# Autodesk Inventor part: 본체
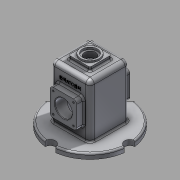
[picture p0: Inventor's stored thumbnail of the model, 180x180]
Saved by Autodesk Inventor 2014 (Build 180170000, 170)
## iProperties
Created: 2018-07
Part Number: 본체
Material: Aluminum 6061
Document SubType Name: Modeling
Designer: user
Density: 2.71 g/cm^3
Appearance: Aluminum - Flat
Mass: 923.886 g
Surface Area: 1002.83 cm^2
Volume: 340.917 cm^3
Author: user
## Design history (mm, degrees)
sketch "Sketch1"
  geometry: C1 r 75 at (0, 0); 1 further point
  constraints: 1 centre point, 1 coincident
  dimensions: "d0" = 150 diameter of C1
extrude "Extrusion1" new body sketch "Sketch1" distance "d1" = 10; taper "d2" = 0 deg
sketch "Sketch2"
  geometry: L1 (0, 0)-(0, 121.11); C1 r 10 at (0, 75)
  constraints: 2 end point, 1 centre point, 1 vertical, 1 vertical alignment, 1 other
  dimensions: "d3" = 20 diameter of C1; "d4" = 0 distance from line of C1.centre L1
extrude "Extrusion2" cut sketch "Sketch2" distance "d5" = 10; taper "d6" = 0 deg
pattern_circular "Circular Pattern1" dims angle "d8" = 360 deg
sketch "Sketch3"
  geometry: L1 (-37, 37)-(37, 37); L2 (37, 37)-(37, -37); L3 (37, -37)-(-37, -37); L4 (-37, -37)-(-37, 37); L5 (0, 0)-(153.232, 0); L6 (0, 0)-(0, 243.546); A1 r 75 centre (0, 0) between (9.978, -74.333) and (74.333, -9.978) reference
  constraints: 12 end point, 3 perpendicular, 2 parallel, 1 horizontal, 2 other
  dimensions: "d10" = 74 distance between parallel lines of L4 L2; "d11" = 74 distance between parallel lines of L3 L1
extrude "Extrusion3" join sketch "Sketch3" distance "d12" = 100; taper "d13" = 0 deg
workplane "Work Plane1"
sketch "Sketch4"
  geometry: L1 (12, 70)-(62, 70); L2 (62, 70)-(62, 20); L3 (62, 20)-(12, 20); L4 (12, 20)-(12, 70); L5 (-38.534, 45)-(101.823, 45); L6 (37, 113.812)-(37, 3.906); L7 (46.978, -10)-(111.333, -10) reference; L8 (74, 0)-(74, 100) reference; 1 further point
  constraints: 12 end point, 3 perpendicular, 2 parallel, 1 horizontal, 2 other
  dimensions: "d16" = 50 distance between parallel lines of L3 L1; "d17" = 50 distance between parallel lines of L4 L2; "d18" = 55 distance between parallel lines of L5 L7; "d20" = 37 distance between parallel lines of L6 L8
extrude "Extrusion4" join sketch "Sketch4" distance "d21" = 100; taper "d22" = 0 deg
sketch "Sketch5"
  geometry: L1 (-12, 70)-(-62, 70) reference; L2 (-12, 20)-(-12, 70) reference; C1 r 16 at (-37, 45); 1 further point
  constraints: 1 centre point
  dimensions: "d23" = 32 diameter of C1; "d26" = 25 distance from line of L2 C1.centre; "d27" = 25 distance from line of C1.centre L1
extrude "Extrusion5" cut sketch "Sketch5" distance "d28" = 100; taper "d29" = 0 deg
chamfer "Chamfer1" distance "d30" = 1; stored, may be unused: second distance "d31" = 2, angle "d32" = 45 deg
fillet "Fillet1" dims "d33" = 6
fillet "Fillet2" dims "d34" = 3
sketch "Sketch6"
  geometry: A1 r 6 centre (18, 26) between (12, 26) and (18, 20) reference; A2 r 6 centre (56, 26) between (56, 20) and (62, 26) reference; A3 r 6 centre (56, 64) between (62, 64) and (56, 70) reference; A4 r 6 centre (18, 64) between (18, 70) and (12, 64) reference; 5 further points
  constraints: 4 coincident
hole "Hole1" sketch "Sketch6" at (18, 64), (56, 64), (56, 26), (18, 26) diameter "d35" = 3.242; stored, may be unused: countersink angle "d39" = 82 deg, drill point angle "d41" = 118 deg; dims "d36" = 8, "d37" = 3.023, "d38" = 2, "d40" = 10
mirror "Mirror1"
fillet "Fillet3" dims "d42" = 8
fillet "Fillet4" dims "d43" = 8
fillet "Fillet5" dims "d44" = 3
fillet "Fillet6" dims "d45" = 3
sketch "Sketch7"
  geometry: L1 (-20, 20)-(20, 20); L2 (20, 20)-(20, -20); L3 (20, -20)-(-20, -20); L4 (-20, -20)-(-20, 20); 1 further point
  constraints: 8 end point, 2 parallel, 1 horizontal, 1 perpendicular
  dimensions: "d46" = 40 distance between parallel lines of L4 L2; "d47" = 40 distance between parallel lines of L3 L1; "d48" = 20 distance from line of L1 point (0, 0); "d49" = 20 distance from line of point (0, 0) L2
extrude "Extrusion6" join sketch "Sketch7" distance "d50" = 7; taper "d51" = 0 deg
sketch "Sketch8"
  geometry: C1 r 17.5 at (0, 0); 1 further point
  constraints: 1 centre point, 1 coincident
  dimensions: "d52" = 35 diameter of C1
extrude "Extrusion7" join sketch "Sketch8" distance "d53" = 3; taper "d54" = 0 deg
sketch "Sketch9"
  geometry: L1 (0, 0)-(0, 389.433); L2 (0, 105)-(32, 105); L3 (32, 0)-(0, 0); L4 (9.978, 0)-(74.333, 0) reference; L5 (-29, 110)-(29, 110) reference; L6 (32, 75)-(25, 75); L7 (25, 75)-(25, 35); L8 (25, 35)-(32, 35); L9 (32, 105)-(32, 75); L10 (32, 35)-(32, 0); L11 (-62.016, 55)-(68.351, 55); L12 (0, 105)-(-32, 105); L13 (-32, 105)-(-32, 75); L14 (-32, 75)-(-25, 75); L15 (-25, 75)-(-25, 35); L16 (-25, 35)-(-32, 35); L17 (-32, 35)-(-32, 0); L18 (-32, 0)-(0, 0)
  constraints: 32 end point, 6 symmetric about line, 4 perpendicular, 3 parallel, 2 point on line, 1 collinear, 1 horizontal, 1 vertical, 1 other
  dimensions: "d88" = 0 distance between parallel lines of L3 L4; "d90" = 5 distance between parallel lines of L5 L2; "d93" = 32 distance between parallel lines of L1 L10; "d94" = 7 distance between parallel lines of L9 L7; "d95" = 55 distance between parallel lines of L4 L11; "d96" = 40 distance between parallel lines of L8 L6
sketch "Sketch10"
  geometry: L1 (0, 0)-(0, 198.492); L2 (32, 80)-(22, 76.36); L3 (22, 76.36)-(22, 33.64); L4 (22, 33.64)-(32, 30); L5 (32, 80)-(32, 30); L6 (-17.49, 55)-(69.252, 55); L7 (9.978, 0)-(74.333, 0) reference
  constraints: 12 end point, 1 parallel, 1 perpendicular, 1 vertical
  dimensions: "d67" = 110 deg angle of L4 L5; "d68" = 110 deg angle of L2 L5; "d70" = 10 distance between parallel lines of L3 L5; "d71" = 50 distance of L4.end L2.start; "d72" = 25 distance from line of L6 L2.start; "d73" = 55 distance between parallel lines of L7 L6; "d74" = 64 diameter of L5 L1
extrude "Extrusion11" cut sketch "Sketch9" stored distance "d97" = 64; taper "d98" = 0 deg
revolve "Revolution1" stored, may be unused: angle "d99" = 90 deg
sketch "Sketch11"
  geometry: L1 (0, 0)-(0, 277.521); L2 (14, 120)-(14, 116); L3 (14, 116)-(10.5, 116); L4 (10.5, 116)-(10.5, 105); L5 (17.5, 120)-(-17.5, 120) reference; L6 (10.5, 105)-(0, 105); L7 (14, 120)-(0, 120); L8 (0, 120)-(0, 105); L9 (-29, 110)-(29, 110) reference
  constraints: 14 end point, 3 parallel, 2 point on line, 1 collinear, 1 midpoint, 1 perpendicular, 1 vertical
  dimensions: "d100" = 21 diameter of L4 L1; "d101" = 4 distance between parallel lines of L3 L5; "d102" = 28 diameter of L2 L1; "d103" = 5 distance between parallel lines of L6 L9
revolve "Revolution2" sketch "Sketch11" stored, may be unused: angle "d104" = 90 deg
fillet "Fillet7" dims "d105" = 3
fillet "Fillet8" dims "d106" = 3
sketch "Sketch12"
  geometry: L1 (6.108, -10.61)-(51.892, -10.61); L2 (51.892, -10.61)-(51.892, -13.39); L3 (51.892, -13.39)-(6.108, -13.39); L4 (6.108, -13.39)-(6.108, -10.61); L5 (-7.142, -12)-(65.536, -12); L6 (29, -2.071)-(29, -38.646); L7 (66, -89)-(66, 0) reference; L8 (46.5, 18)-(11.5, 18) reference; 1 further point
  constraints: 4 end point, 2 perpendicular, 4 other
  dimensions: "d107" = 37 distance between parallel lines of L7 L6; "d108" = 30 distance between parallel lines of L5 L8
extrude "Extrusion12" join sketch "Sketch12" distance "d109" = 0.5; taper "d110" = 0 deg
body "Solid1"
other parameters: "d14" = 13, "d61" = 64, "d79" = 110 deg, "d80" = 110 deg, "d89" = 64
